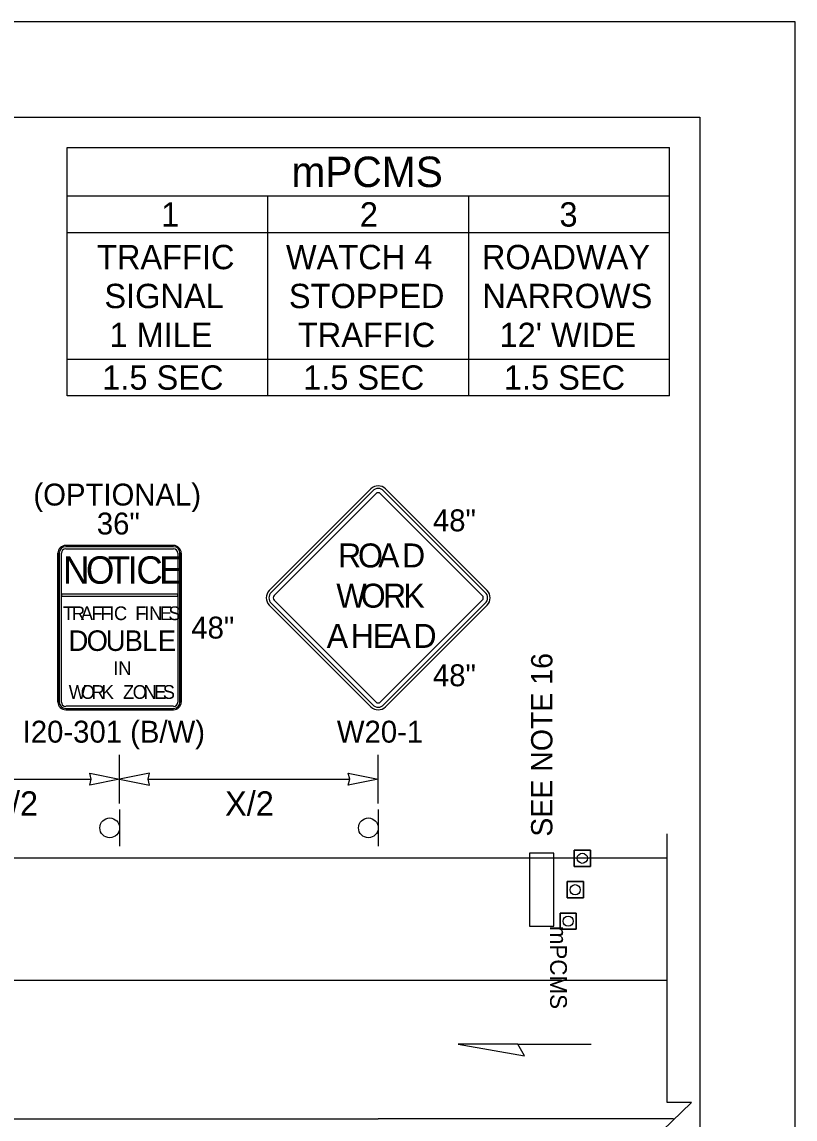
# Model space of a CAD drawing. Extents: x 99977 to 100176, y 99905 to 100011.
# Drawn here: x 100093.522 to 100096.062, y 100007.082 to 100010.687 of the extents above; entities that cross this region are included whole.
import ezdxf

# ---------------------------------------------------------------- set-up
doc = ezdxf.new("R2010")
doc.units = 0
for name, color, linetype in [('RD_ED_ShoulderPavedEdge', 7, 'Continuous'), ('RD_MK_LineDblYellowCenter', 7, 'Continuous'), ('RD_MK_LineEdgeWhite', 7, 'Continuous'), ('RD_MK_LineSkipCenter', 7, 'Continuous'), ('SH_GI_PlotLimits', 7, 'Continuous'), ('SH_GI_SheetBorder', 7, 'Continuous'), ('TR_SN_ConstructionSigns', 7, 'Continuous'), ('TR_WZ_PCMS', 7, 'Continuous'), ('TR_WZ_PortableChangeMessageSign', 7, 'Continuous'), ('TR_WZ_Sign', 7, 'Continuous'), ('TR_WZ_TrafficCone', 7, 'Continuous'), ('TR_WZ_WorkZoneDetails', 7, 'Continuous'), ('TR_WZ_WorkZoneTextCurrent', 7, 'Continuous')]:
    doc.layers.add(name, color=color, linetype=linetype)

msp = doc.modelspace()

# ---------------------------------------------------------------- linework, layer by layer
at = {"layer": 'RD_ED_ShoulderPavedEdge'}
msp.add_line((100095.6424, 100007.9393), (100080.3, 100007.9393), dxfattribs=at)
at = {"layer": 'RD_MK_LineDblYellowCenter'}
msp.add_line((100095.6631, 100007.0826), (100094.6924, 100007.0826), dxfattribs=at)
at = {"layer": 'RD_MK_LineEdgeWhite'}
msp.add_line((100084.8112, 100007.5393), (100095.6425, 100007.5393), dxfattribs=at)
at = {"layer": 'RD_MK_LineSkipCenter'}
msp.add_lwpolyline([(100089.3425, 100007.0826), (100094.6924, 100007.0826)], dxfattribs=at)
at = {"layer": 'SH_GI_PlotLimits'}
msp.add_lwpolyline([(100079.0625, 99999.6875), (100096.0625, 99999.6875), (100096.0625, 100010.6875), (100079.0625, 100010.6875)], close=True, dxfattribs=at)
at = {"layer": 'SH_GI_SheetBorder'}
for p, q in [((100080, 100010.375), (100095.75, 100010.375)), ((100095.75, 100010.375), (100095.75, 100000))]:
    msp.add_line(p, q, dxfattribs=at)
at = {"layer": 'TR_SN_ConstructionSigns'}
for p, q in [((100094.6686, 100009.1531), (100094.3345, 100008.819)), ((100094.6746, 100009.1472), (100094.3405, 100008.8131)), ((100094.3504, 100008.8031), (100094.6845, 100009.1372)), ((100094.7004, 100009.1372), (100095.0345, 100008.8031)), ((100095.0445, 100008.8131), (100094.7104, 100009.1472)), ((100095.0505, 100008.819), (100094.7163, 100009.1531)), ((100093.6653, 100008.9673), (100094.0197, 100008.9673)), ((100094.0197, 100008.9673), (100093.6653, 100008.9673)), ((100094.0197, 100008.9673), (100093.6653, 100008.9673)), ((100094.0197, 100008.9631), (100093.6653, 100008.9631)), ((100093.6653, 100008.9561), (100094.0197, 100008.9561)), ((100093.64, 100008.4526), (100093.64, 100008.942)), ((100093.64, 100008.942), (100093.64, 100008.4526)), ((100093.64, 100008.942), (100093.64, 100008.4526)), ((100093.6442, 100008.942), (100093.6442, 100008.4526)), ((100093.6512, 100008.8077), (100093.6512, 100008.942)), ((100094.0337, 100008.942), (100094.0337, 100008.8077)), ((100094.0408, 100008.4526), (100094.0408, 100008.942)), ((100094.045, 100008.942), (100094.045, 100008.4526)), ((100094.045, 100008.4526), (100094.045, 100008.942)), ((100094.045, 100008.4526), (100094.045, 100008.942)), ((100093.6512, 100008.8077), (100093.6512, 100008.8077)), ((100094.0337, 100008.8077), (100093.6512, 100008.8077)), ((100093.6512, 100008.8077), (100093.6512, 100008.8007)), ((100093.6512, 100008.8007), (100093.6512, 100008.8077)), ((100094.0337, 100008.8007), (100094.0337, 100008.8077)), ((100094.0337, 100008.8077), (100094.0337, 100008.8007)), ((100093.6512, 100008.8007), (100094.0337, 100008.8007)), ((100093.6512, 100008.4526), (100093.6512, 100008.8007)), ((100094.0337, 100008.8007), (100094.0337, 100008.4526)), ((100094.3405, 100008.7773), (100094.6746, 100008.4432)), ((100094.6845, 100008.4531), (100094.3504, 100008.7872)), ((100095.0345, 100008.7872), (100094.7004, 100008.4531)), ((100094.7104, 100008.4432), (100095.0445, 100008.7773)), ((100094.3345, 100008.7713), (100094.6686, 100008.4372)), ((100094.7163, 100008.4372), (100095.0505, 100008.7713)), ((100094.0197, 100008.4386), (100093.6653, 100008.4386)), ((100093.6653, 100008.4315), (100094.0197, 100008.4315)), ((100094.0197, 100008.4273), (100093.6653, 100008.4273)), ((100093.6653, 100008.4273), (100094.0197, 100008.4273)), ((100093.6653, 100008.4273), (100094.0197, 100008.4273))]:
    msp.add_line(p, q, dxfattribs=at)
for centre, radius, start, end in [((100094.6925, 100009.1293), 0.0338, 45, 135), ((100094.6925, 100009.1293), 0.0253, 45, 135), ((100094.6925, 100009.1293), 0.0113, 45, 135), ((100093.6653, 100008.942), 0.0253, 90, 180), ((100093.6653, 100008.942), 0.0253, 90, 180), ((100093.6653, 100008.942), 0.0253, 90, 180), ((100093.6653, 100008.942), 0.0211, 90, 180), ((100093.6653, 100008.942), 0.0141, 90, 180), ((100094.0197, 100008.942), 0.0253, 0, 90), ((100094.0197, 100008.942), 0.0253, 0, 90), ((100094.0197, 100008.942), 0.0253, 0, 90), ((100094.0197, 100008.942), 0.0211, 0, 90), ((100094.0197, 100008.942), 0.0141, 0, 90), ((100094.3584, 100008.7952), 0.0338, 135, 225), ((100094.3584, 100008.7952), 0.0253, 135, 225), ((100095.0266, 100008.7952), 0.0253, 315, 45), ((100095.0266, 100008.7952), 0.0338, 315, 45), ((100094.3584, 100008.7952), 0.0113, 135, 225), ((100095.0266, 100008.7952), 0.0113, 315, 45), ((100093.6653, 100008.4526), 0.0253, 180, 270), ((100093.6653, 100008.4526), 0.0253, 180, 270), ((100093.6653, 100008.4526), 0.0253, 180, 270), ((100093.6653, 100008.4526), 0.0211, 180, 270), ((100093.6653, 100008.4526), 0.0141, 180, 270), ((100094.0197, 100008.4526), 0.0253, 270, 0), ((100094.0197, 100008.4526), 0.0253, 270, 0), ((100094.0197, 100008.4526), 0.0211, 270, 0), ((100094.0197, 100008.4526), 0.0141, 270, 0), ((100094.0197, 100008.4526), 0.0253, 270, 0), ((100094.6925, 100008.4611), 0.0113, 225, 315), ((100094.6925, 100008.4611), 0.0338, 225, 315), ((100094.6925, 100008.4611), 0.0253, 225, 315)]:
    msp.add_arc(centre, radius, start, end, dxfattribs=at)
at = {"layer": 'TR_WZ_PCMS'}
msp.add_lwpolyline([(100095.19, 100007.9559), (100095.19, 100007.7159), (100095.27, 100007.7159), (100095.27, 100007.9559)], close=True, dxfattribs=at)
msp.add_lwpolyline([(100095.19, 100007.9559), (100095.19, 100007.7159), (100095.27, 100007.7159), (100095.27, 100007.9559), (100095.19, 100007.9559)], dxfattribs=at)
at = {"layer": 'TR_WZ_PortableChangeMessageSign'}
for p, q in [((100093.67, 100010.275), (100095.65, 100010.275)), ((100093.67, 100009.459), (100093.67, 100010.275)), ((100095.65, 100009.459), (100095.65, 100010.275)), ((100095.65, 100010.115), (100093.67, 100010.115)), ((100094.33, 100009.459), (100094.33, 100010.115)), ((100094.99, 100009.459), (100094.99, 100010.115)), ((100094.33, 100009.995), (100093.67, 100009.995)), ((100094.99, 100009.995), (100094.33, 100009.995)), ((100095.65, 100009.995), (100094.99, 100009.995)), ((100093.67, 100009.579), (100094.33, 100009.579)), ((100094.33, 100009.579), (100094.99, 100009.579)), ((100094.99, 100009.579), (100095.65, 100009.579)), ((100095.65, 100009.459), (100093.67, 100009.459))]:
    msp.add_line(p, q, dxfattribs=at)
at = {"layer": 'TR_WZ_Sign'}
for p, q in [((100093.8425, 100008.0994), (100093.8425, 100007.9793)), ((100094.6925, 100008.0994), (100094.6925, 100007.9793))]:
    msp.add_line(p, q, dxfattribs=at)
for centre in [(100093.8101, 100008.0393), (100093.8101, 100008.0393), (100094.6601, 100008.0393), (100094.6601, 100008.0393)]:
    msp.add_circle(centre, 0.0324, dxfattribs=at)
at = {"layer": 'TR_WZ_TrafficCone'}
for points in [[(100095.39, 100007.9126), (100095.3367, 100007.9126), (100095.3367, 100007.9659), (100095.39, 100007.9659), (100095.39, 100007.9126)], [(100095.39, 100007.9659), (100095.3367, 100007.9659), (100095.3367, 100007.9126), (100095.39, 100007.9126), (100095.39, 100007.9659)], [(100095.3667, 100007.8092), (100095.3133, 100007.8092), (100095.3133, 100007.8626), (100095.3667, 100007.8626), (100095.3667, 100007.8092)], [(100095.3667, 100007.8626), (100095.3133, 100007.8626), (100095.3133, 100007.8092), (100095.3667, 100007.8092), (100095.3667, 100007.8626)], [(100095.3433, 100007.7059), (100095.29, 100007.7059), (100095.29, 100007.7592), (100095.3433, 100007.7592), (100095.3433, 100007.7059)], [(100095.3433, 100007.7592), (100095.29, 100007.7592), (100095.29, 100007.7059), (100095.3433, 100007.7059), (100095.3433, 100007.7592)]]:
    msp.add_lwpolyline(points, dxfattribs=at)
for centre in [(100095.3633, 100007.9392), (100095.34, 100007.8359), (100095.3167, 100007.7326)]:
    msp.add_circle(centre, 0.0167, dxfattribs=at)
at = {"layer": 'TR_WZ_WorkZoneDetails'}
for p, q in [((100093.8425, 100008.1193), (100093.8425, 100008.2793)), ((100094.6925, 100008.1193), (100094.6925, 100008.2793)), ((100093.2362, 100008.1993), (100093.7487, 100008.1993)), ((100093.9362, 100008.1993), (100094.5987, 100008.1993)), ((100095.1514, 100007.3286), (100095.3925, 100007.3286))]:
    msp.add_line(p, q, dxfattribs=at)
for points in [[(100093.8425, 100008.1993), (100093.7442, 100008.18), (100093.7487, 100008.1993), (100093.7442, 100008.2186)], [(100093.8425, 100008.1993), (100093.9408, 100008.18), (100093.9362, 100008.1993), (100093.9408, 100008.2186)], [(100094.6925, 100008.1993), (100094.5942, 100008.18), (100094.5987, 100008.1993), (100094.5942, 100008.2186)], [(100094.9548, 100007.3286), (100095.1737, 100007.29), (100095.1514, 100007.3286)]]:
    msp.add_lwpolyline(points, close=True, dxfattribs=at)
msp.add_lwpolyline([(100095.6425, 100006.0993), (100095.6425, 100006.9819), (100095.5624, 100006.9819), (100095.7225, 100007.1367), (100095.6425, 100007.1367), (100095.6425, 100008.0193)], dxfattribs=at)

# ---------------------------------------------------------------- texts
at = {"layer": 'TR_SN_ConstructionSigns'}
for s, p in [('(OPTIONAL)', (100093.5593, 100009.0984)), ('36"', (100093.7677, 100009.0033)), ('48"', (100094.8723, 100009.0137)), ('48"', (100094.0782, 100008.6613)), ('48"', (100094.8723, 100008.5046)), ('I20-301 (B/W)', (100093.5239, 100008.3193)), ('W20-1', (100094.5566, 100008.3193))]:
    msp.add_text(s, height=0.072, rotation=360, dxfattribs=at).set_placement(p)
for s, height, p in [('R', 0.0788, (100094.5606, 100008.895)), ('O', 0.0788, (100094.6259, 100008.895)), ('A', 0.0788, (100094.6921, 100008.895)), ('D', 0.0788, (100094.7708, 100008.895)), ('N', 0.09, (100093.6567, 100008.8415)), ('O', 0.09, (100093.7318, 100008.8415)), ('T', 0.09, (100093.8039, 100008.8415)), ('I', 0.09, (100093.8691, 100008.8415)), ('C', 0.09, (100093.8974, 100008.8415)), ('E', 0.09, (100093.9724, 100008.8415)), ('W', 0.0788, (100094.5547, 100008.7628)), ('O', 0.0788, (100094.635, 100008.7628)), ('R', 0.0788, (100094.7082, 100008.7628)), ('K', 0.0788, (100094.7752, 100008.7628)), ('T', 0.045, (100093.6566, 100008.7219)), ('R', 0.045, (100093.6859, 100008.7219)), ('A', 0.045, (100093.7151, 100008.7219)), ('F', 0.045, (100093.7502, 100008.7219)), ('F', 0.045, (100093.7795, 100008.7219)), ('I', 0.045, (100093.8087, 100008.7219)), ('C', 0.045, (100093.824, 100008.7219)), ('F', 0.045, (100093.8942, 100008.7219)), ('I', 0.045, (100093.9235, 100008.7219)), ('N', 0.045, (100093.9397, 100008.7219)), ('E', 0.045, (100093.9748, 100008.7219)), ('S', 0.045, (100094.0031, 100008.7219)), ('A', 0.0788, (100094.5232, 100008.6306)), ('H', 0.0788, (100094.6019, 100008.6306)), ('E', 0.0788, (100094.6744, 100008.6306)), ('A', 0.0788, (100094.7295, 100008.6306)), ('D', 0.0788, (100094.8082, 100008.6306)), ('D', 0.0675, (100093.6747, 100008.6207)), ('O', 0.0675, (100093.7341, 100008.6207)), ('U', 0.0675, (100093.7969, 100008.6207)), ('B', 0.0675, (100093.859, 100008.6207)), ('L', 0.0675, (100093.9164, 100008.6207)), ('E', 0.0675, (100093.9684, 100008.6207)), ('I', 0.045, (100093.8218, 100008.5419)), ('N', 0.045, (100093.838, 100008.5419)), ('W', 0.045, (100093.6753, 100008.4632)), ('O', 0.045, (100093.7149, 100008.4632)), ('R', 0.045, (100093.7505, 100008.4632)), ('K', 0.045, (100093.7833, 100008.4632)), ('Z', 0.045, (100093.8535, 100008.4632)), ('O', 0.045, (100093.8855, 100008.4632)), ('N', 0.045, (100093.921, 100008.4632)), ('E', 0.045, (100093.9561, 100008.4632)), ('S', 0.045, (100093.9845, 100008.4632))]:
    msp.add_text(s, height=height, dxfattribs=at).set_placement(p)
at = {"layer": 'TR_WZ_PCMS'}
msp.add_text('mPCMS', height=0.055, rotation=270, dxfattribs=at).set_placement((100095.2575, 100007.7176))
at = {"layer": 'TR_WZ_PortableChangeMessageSign'}
for s, height, p in [('mPCMS', 0.1, (100094.4072, 100010.145)), ('1', 0.08, (100093.9789, 100010.015)), ('2', 0.08, (100094.6321, 100010.015)), ('3', 0.08, (100095.2882, 100010.015)), ('TRAFFIC', 0.08, (100093.7684, 100009.875)), ('WATCH 4', 0.08, (100094.3892, 100009.875)), ('ROADWAY', 0.08, (100095.0333, 100009.875)), ('SIGNAL', 0.08, (100093.7925, 100009.747)), ('STOPPED', 0.08, (100094.3989, 100009.747)), ('NARROWS', 0.08, (100095.0348, 100009.747)), ('1 MILE', 0.08, (100093.8091, 100009.619)), ('TRAFFIC', 0.08, (100094.4284, 100009.619)), ("12' WIDE", 0.08, (100095.0912, 100009.619)), ('1.5 SEC', 0.08, (100093.7856, 100009.479)), ('1.5 SEC', 0.08, (100094.4456, 100009.479)), ('1.5 SEC', 0.08, (100095.1056, 100009.479))]:
    msp.add_text(s, height=height, rotation=360, dxfattribs=at).set_placement(p)
at = {"layer": 'TR_WZ_WorkZoneTextCurrent'}
msp.add_text('SEE NOTE 16', height=0.07, rotation=90, dxfattribs=at).set_placement((100095.265, 100008.0103))
for p in [(100093.414, 100008.0793), (100094.189, 100008.0793)]:
    msp.add_text('X/2', height=0.08, dxfattribs=at).set_placement(p)

doc.saveas('drawing.dxf')
